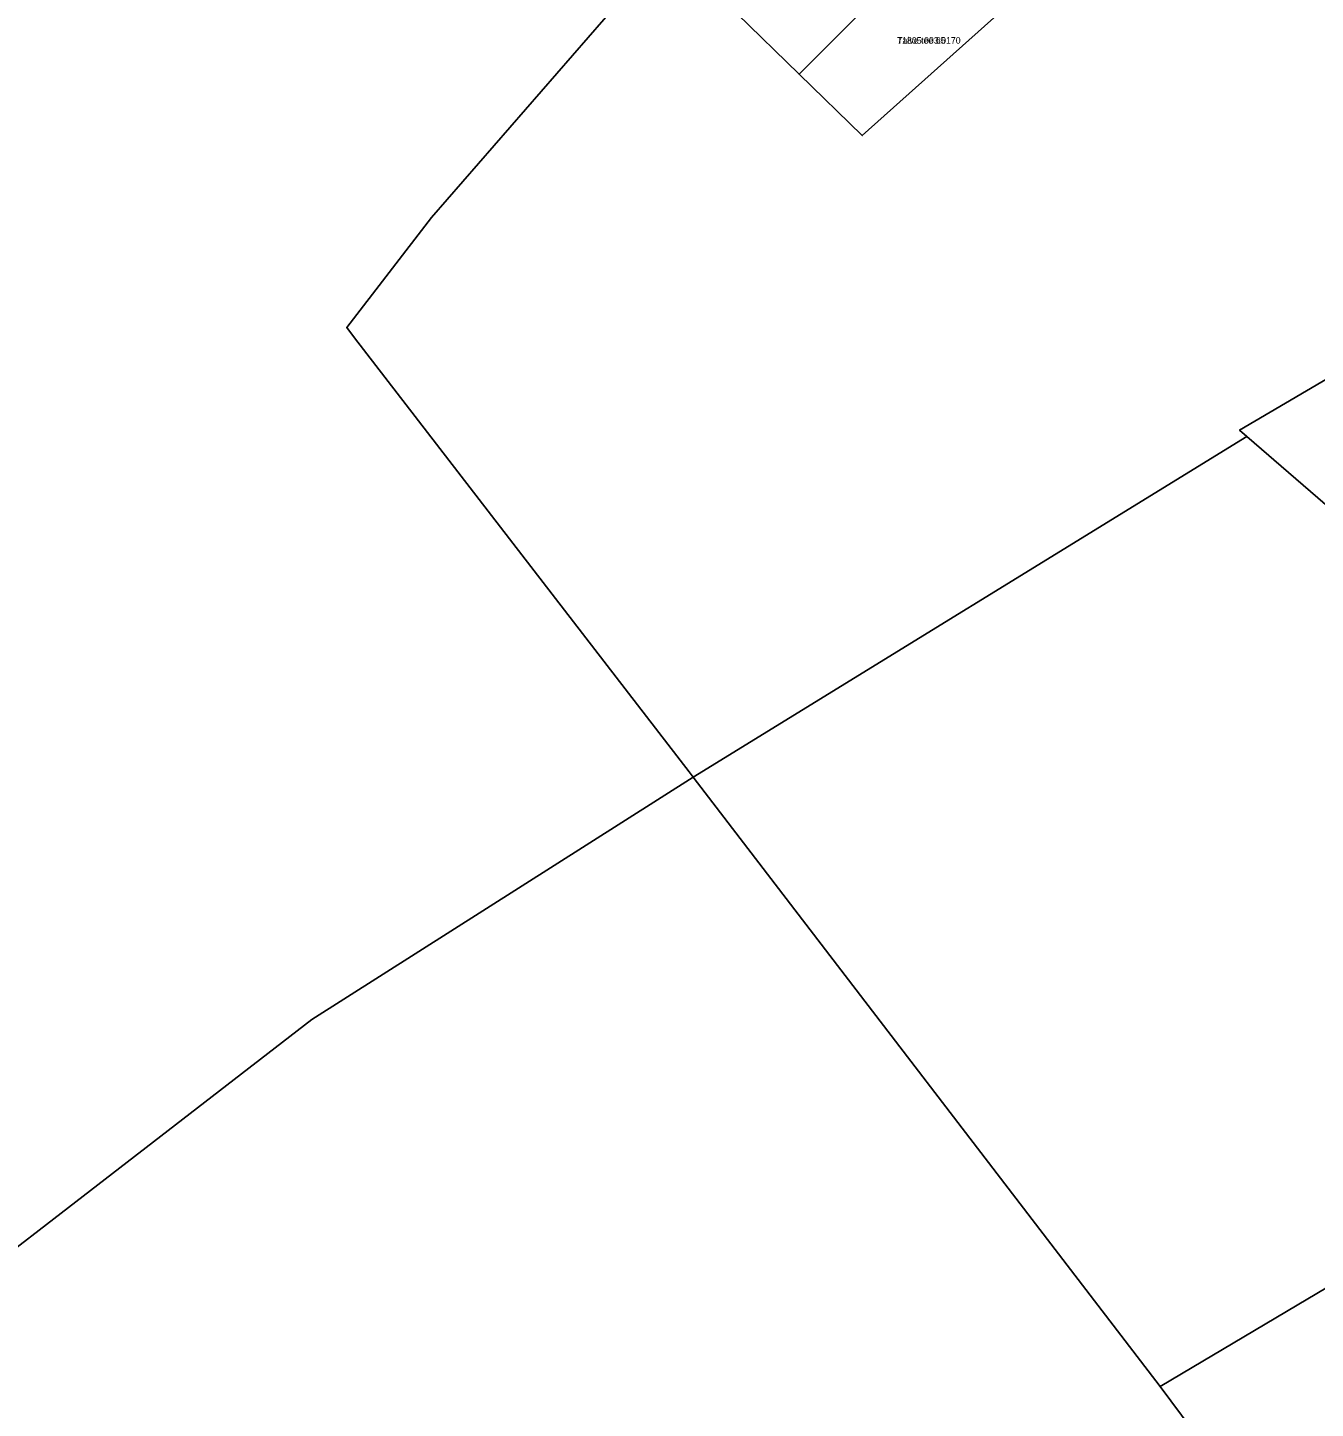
# Model space of a CAD drawing. Extents: x 529768 to 552006, y 6562269 to 6580975.
# Drawn here: x 536847 to 537141.4, y 6570909.2 to 6571224.9 of the extents above; entities that cross this region are included whole.
import ezdxf

# ---------------------------------------------------------------- set-up
doc = ezdxf.new("R2010")
doc.units = 0
for name, color, linetype in [('L_AADRESS', 7, 'Continuous'), ('PIIR', 7, 'Continuous'), ('TUNNUS', 7, 'Continuous')]:
    doc.layers.add(name, color=color, linetype=linetype)

msp = doc.modelspace()

# ---------------------------------------------------------------- linework, layer by layer
at = {"layer": 'PIIR'}
for points in [[(536793, 6571361.49), (536874.33, 6571360.77), (536908.09, 6571327.91), (536930.21, 6571305.71), (536949.43, 6571286.3), (536970.84, 6571264.85), (536991.59, 6571244.96), (536993.07, 6571243.33), (536939.3, 6571181.48), (536919.93, 6571156.36), (536921.7, 6571153.98), (536998.23, 6571054.73), (536999.17, 6571053.52), (536911.97, 6570998.11), (536782.85, 6570898.37)], [(537322.52, 6571249.63), (537273.68, 6571221.14), (537251.33, 6571208.43), (537228.97, 6571194.99), (537206.95, 6571181.9), (537183.52, 6571168.06), (537149.89, 6571148.07), (537124.11, 6571132.89), (537125.77, 6571131.43), (536999.17, 6571053.52), (536998.23, 6571054.73), (536921.7, 6571153.98), (536919.93, 6571156.36), (536939.3, 6571181.48), (536993.07, 6571243.33)], [(537009.11, 6571228.12), (537023.36, 6571214.26), (537037.83, 6571200.24), (537069.32, 6571228.45)]]:
    msp.add_lwpolyline(points, dxfattribs=at)
for points in [[(537009.11, 6571228.12), (537035.3, 6571257.37), (537051.39, 6571242.23), (537023.36, 6571214.26)], [(537023.36, 6571214.26), (537051.39, 6571242.23), (537058.16, 6571235.84), (537059.9, 6571237.63), (537069.32, 6571228.45), (537037.83, 6571200.24)], [(537125.77, 6571131.43), (537124.11, 6571132.89), (537149.89, 6571148.07), (537160.28, 6571141.16), (537170.64, 6571137.45), (537186.24, 6571135.45), (537203.04, 6571133.15), (537204.99, 6571126.02), (537167.76, 6571107.55), (537186.7, 6571086.68), (537181.82, 6571083.05)], [(537105.97, 6570914.22), (536999.17, 6571053.52), (537125.77, 6571131.43), (537181.82, 6571083.05), (537201.28, 6571066.25), (537247.89, 6571025.95), (537286.95, 6570992.3), (537327.98, 6570956.93), (537361.94, 6570928.76), (537384.82, 6570909.76), (537406.88, 6570890.58), (537309.68, 6570814), (537277.74, 6570833.43), (537151.54, 6570941.28)], [(537535.96, 6570627.14), (537397, 6570530.82), (537110.09, 6570332), (537000.05, 6570255.66), (536818.6, 6570529.61), (536973.31, 6570626.66), (536782.85, 6570898.37), (536911.97, 6570998.11), (536999.17, 6571053.52), (537105.97, 6570914.22), (537205, 6570780.99), (537277.74, 6570833.43), (537309.68, 6570814)], [(537105.97, 6570914.22), (537151.54, 6570941.28), (537277.74, 6570833.43), (537205, 6570780.99)]]:
    msp.add_lwpolyline(points, close=True, dxfattribs=at)

# ---------------------------------------------------------------- texts
at = {"layer": 'L_AADRESS'}
msp.add_text('Talve tee 65', height=1.5, dxfattribs=at).set_placement((537045.81, 6571221.24))
at = {"layer": 'TUNNUS'}
msp.add_text('71805:003:0170', height=1.5, dxfattribs=at).set_placement((537045.81, 6571221.24))

doc.saveas('drawing.dxf')
